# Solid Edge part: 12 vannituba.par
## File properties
Author: Henri
Template: Normal.par
Last saved by: Henri
Revision: 11
Application: Solid Edge
Accuracy: 0,990
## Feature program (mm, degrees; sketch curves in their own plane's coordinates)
sketch for "unnamed Protrusion 1" plane through (0, 0, 0) normal (0, 0, 1) x-axis (1, 0, 0)
  line (40, -40) -> (-40, -40)
  line (-40, -40) -> (-40, 40)
  line (-40, 40) -> (40, 40)
  line (40, 40) -> (40, -40)
extrude "unnamed Protrusion 1" add finite 15 along -normal
sketch for "ExtrudedCutout_1" plane through (0, 0, 0) normal (0, 0, 1) x-axis (0, 1, 0)
  line (-37.5, 37.5) -> (37.5, 37.5)
  line (37.5, 37.5) -> (37.5, -37.5)
  line (37.5, -37.5) -> (-37.5, -37.5)
  line (-37.5, -37.5) -> (-37.5, 37.5)
extrude "ExtrudedCutout_1" cut finite 5 along -normal
sketch for "ExtrudedProtrusion_2" #1 plane through (0, 0, 0) normal (0, 0, 1) x-axis (0, 1, 0)
  line (-40, 40) -> (40, 40)
  line (40, 40) -> (40, -40)
  line (40, -40) -> (-40, -40)
  line (-40, -40) -> (-40, 40)
sketch for "ExtrudedProtrusion_2" #2 plane through (0, 0, 0) normal (0, 0, 1) x-axis (0, 1, 0)
  line (-37.5, 37.5) -> (37.5, 37.5)
  line (37.5, 37.5) -> (37.5, -37.5)
  line (37.5, -37.5) -> (-37.5, -37.5)
  line (-37.5, -37.5) -> (-37.5, 37.5)
extrude "ExtrudedProtrusion_2" add finite 110 along +normal
sketch for "unnamed Cutout 1" plane through (40, 0, 50) normal (1, 0, 0) x-axis (0, 1, 0)
  line (-7.5, 47.5) -> (-7.5, -47.5)
  arc centre (-10, -47.5) radius 2.5 from (-10, -50) to (-7.5, -47.5) ccw
  line (-10, -50) -> (-30, -50)
  arc centre (-30, -47.5) radius 2.5 from (-32.5, -47.5) to (-30, -50) ccw
  line (-32.5, -47.5) -> (-32.5, 47.5)
  arc centre (-30, 47.5) radius 2.5 from (-32.5, 47.5) to (-30, 50) cw
  line (-30, 50) -> (-10, 50)
  arc centre (-10, 47.5) radius 2.5 from (-10, 50) to (-7.5, 47.5) cw
extrude "unnamed Cutout 1" cut through along -normal
sketch for "ExtrudedProtrusion_3" plane through (40, 0, 50) normal (1, 0, 0) x-axis (0, 1, 0)
  line (-5, 57.5) -> (-5, -55)
  line (-7.5, -55) -> (-5, -55)
  line (-7.5, 57.5) -> (-7.5, -55)
  line (-7.5, 57.5) -> (-5, 57.5)
extrude "ExtrudedProtrusion_3" add finite 40 along -normal
swept protrusion "unnamed SweptProtrusion 1"
sketch for "unnamed RevolvedProtrusion 1" plane through (0, 16.25, 0) normal (0, -1, 0) x-axis (1, 0, 0)
  line (21.829, 95.767) -> (26.5332, 94.073)
  line (26.5332, 94.073) -> (26.7357, 94.6352)
  arc centre (26.2653, 94.8046) radius 0.5 from (26.7357, 94.6352) to (26.5452, 95.2189) ccw
  arc centre (29.7321, 99.9349) radius 5.6918 from (24.229, 98.4814) to (26.5452, 95.2189) ccw
  arc centre (24.7124, 98.6091) radius 0.5 from (24.242, 98.7785) to (24.229, 98.4814) ccw
  line (24.5294, 99.5765) -> (24.242, 98.7785)
  line (24.5294, 99.5765) -> (23.3533, 100)
  line (23.3533, 100) -> (23.2686, 99.7648)
  line (24.2095, 99.426) -> (23.2686, 99.7648)
  line (24.0068, 98.8632) -> (24.2095, 99.426)
  arc centre (24.7124, 98.6091) radius 0.75 from (23.9873, 98.4175) to (24.0068, 98.8632) cw
  arc centre (29.7321, 99.9349) radius 5.9418 from (26.4053, 95.0118) to (23.9873, 98.4175) cw
  arc centre (26.2653, 94.8046) radius 0.25 from (26.5005, 94.7199) to (26.4053, 95.0118) ccw
  line (26.3827, 94.3929) -> (26.5005, 94.7199)
  line (21.9137, 96.0023) -> (26.3827, 94.3929)
  line (21.9137, 96.0023) -> (21.829, 95.767)
revolve "unnamed RevolvedProtrusion 1" add finite 360 deg
sketch for "ExtrudedProtrusion_4" #1 plane through (32.5, 0, 0) normal (1, 0, 0) x-axis (0, 1, 0)
  circle centre (16.25, 85) radius 1
sketch for "ExtrudedProtrusion_4" #2 plane through (32.5, 0, 0) normal (1, 0, 0) x-axis (0, 1, 0)
  circle centre (16.25, 40) radius 1
extrude "ExtrudedProtrusion_4" add finite 7.5 along +normal
sketch for "ExtrudedProtrusion_5" plane through (32.5, 0, 0) normal (1, 0, 0) x-axis (0, 1, 0)
  circle centre (16.25, 40) radius 1
extrude "ExtrudedProtrusion_5" add finite 2.5 along -normal
fillet "Round_1" radius 0.1
sketch for "unnamed Cutout 2" #1 plane through (21.829, 16.25, 95.767) normal (-0.338814, 0, -0.940853) x-axis (0, 1, 0)
  circle centre (-1.15, 0) radius 0.125
sketch for "unnamed Cutout 2" #2 plane through (21.829, 16.25, 95.767) normal (-0.338814, 0, -0.940853) x-axis (0, 1, 0)
  circle centre (-2, 0) radius 0.125
sketch for "unnamed Cutout 2" #3 plane through (21.829, 16.25, 95.767) normal (-0.338814, 0, -0.940853) x-axis (0, 1, 0)
  circle centre (-2.75, 0) radius 0.125
sketch for "unnamed Cutout 2" #4 plane through (21.829, 16.25, 95.767) normal (-0.338814, 0, -0.940853) x-axis (0, 1, 0)
  circle centre (-3.5, 0) radius 0.125
sketch for "unnamed Cutout 2" #5 plane through (21.829, 16.25, 95.767) normal (-0.338814, 0, -0.940853) x-axis (0, 1, 0)
  circle centre (-4.25, 0) radius 0.125
extrude "unnamed Cutout 2" cut through along -normal
pattern "Pattern_1" of "unnamed Cutout 2" along a curve  XDirCount = 15; XDirSpacing = 50 mm
extrude "unnamed Cutout 3" cut through
extrude "unnamed Cutout 4" cut through
extrude "unnamed Cutout 5" cut through
extrude "unnamed Cutout 6" cut through
extrude "unnamed Cutout 7" cut through
extrude "unnamed Cutout 8" cut through
sketch for "unnamed Cutout 9" #3
  line (47.5, 15.75) -> (47.5, 13.25)
  line (45, 10.75) -> (32.5, 10.75)
  arc centre (45, 13.25) radius 2.5 from (45, 10.75) to (47.5, 13.25) ccw
extrude "unnamed Cutout 9" cut through
extrude "unnamed Cutout 10" cut through
extrude "unnamed Cutout 11" cut through
extrude "unnamed Cutout 12" cut through
extrude "unnamed Cutout 13" cut through
extrude "unnamed Cutout 14" cut through
extrude "unnamed Cutout 15" cut through
extrude "unnamed Cutout 16" cut through
sketch for "ExtrudedProtrusion_7" plane through (30, 16.25, 40) normal (-1, 0, 0) x-axis (0, -1, 0)
  line (-4.75, 1.25) -> (4.75, 1.25)
  arc centre (4.75, 1) radius 0.25 from (4.75, 1.25) to (5, 1) cw
  line (5, 1) -> (5, -1)
  arc centre (4.75, -1) radius 0.25 from (4.75, -1.25) to (5, -1) ccw
  line (4.75, -1.25) -> (-4.75, -1.25)
  arc centre (-4.75, -1) radius 0.25 from (-5, -1) to (-4.75, -1.25) ccw
  line (-5, 1) -> (-5, -1)
  arc centre (-4.75, 1) radius 0.25 from (-5, 1) to (-4.75, 1.25) cw
extrude "ExtrudedProtrusion_7" add finite 3 along +normal
fillet "Round_4" radius 0.1
lofted protrusion "unnamed LoftedProtrusion 1"
lofted protrusion "unnamed LoftedProtrusion 2"
fillet "Round_5" radius 0.1
lofted cutout "unnamed LoftedCutout 1"
sketch for "unnamed Cutout 17" #1 plane through (0, 0, -5) normal (0, 0, 1) x-axis (1, 0, 0)
  circle centre (26.5, 16.25) radius 0.25
sketch for "unnamed Cutout 17" #2 plane through (0, 0, -5) normal (0, 0, 1) x-axis (1, 0, 0)
  circle centre (27.5, 16.25) radius 0.25
extrude "unnamed Cutout 17" cut through along -normal
pattern "Pattern_6" of "unnamed Cutout 17" along a curve  XDirCount = 8; XDirSpacing = 50 mm
extrude "unnamed Cutout 18" cut through
extrude "unnamed Cutout 19" cut through
extrude "unnamed Cutout 20" cut through
extrude "unnamed Cutout 21" cut through
extrude "unnamed Cutout 22" cut through
extrude "unnamed Cutout 23" cut through
extrude "unnamed Cutout 24" cut through
sketch for "unnamed Protrusion 2" plane through (0, 37.5, 52.5) normal (0, -1, 0) x-axis (1, 0, 0)
  circle centre (-30, 42.5) radius 0.75
extrude "unnamed Protrusion 2" add through along +normal
sketch for "RevolvedProtrusion_6" plane through (-37.5, 0, 52.5) normal (1, 0, 0) x-axis (0, 1, 0)
  line (0, 0) -> (0, 0)
  line (0, 0) -> (0, 0)
  line (-37.5, -30) -> (-14, -30)
  arc centre (-14, -31.5) radius 1.5 from (-14, -30) to (-12.5, -31.5) cw
  line (-12.5, -31.5) -> (-12.5, -36)
  arc centre (-14, -36) radius 1.5 from (-12.5, -36) to (-14, -37.5) cw
  line (-28.4376, -37.5) -> (-14, -37.5)
  arc centre (-28.4376, -39) radius 1.5 from (-29.2101, -37.7142) to (-28.4376, -37.5) cw
  line (-29.2101, -37.7142) -> (-37.5, -42.6952)
  line (-37.5, -42.6952) -> (-37.5, -32.5)
  line (-37.5, -30) -> (-37.5, -32.5)
revolve "RevolvedProtrusion_6" add finite 90 deg
sketch for "unnamed Protrusion 3" plane through (-37.5, 0, 52.5) normal (1, 0, 0) x-axis (0, 1, 0)
  line (-37.5, 55) -> (37.5, 55)
  line (37.5, 55) -> (37.5, 57.5)
  line (-37.5, 57.5) -> (37.5, 57.5)
  line (-37.5, 57.5) -> (-37.5, 55)
extrude "unnamed Protrusion 3" add through along +normal
sketch for "unnamed RevolvedProtrusion 2" plane through (0, 21.25, 0) normal (0, -1, 0) x-axis (1, 0, 0)
revolve "unnamed RevolvedProtrusion 2" add finite 360 deg
sketch for "unnamed Protrusion 4" #1 plane through (40, 0, 47.5) normal (1, 0, 0) x-axis (0, 1, 0)
sketch for "unnamed Protrusion 4" #2 plane through (40, 0, 47.5) normal (1, 0, 0) x-axis (0, 1, 0)
extrude "unnamed Protrusion 4" add through along +normal
swept protrusion "unnamed SweptProtrusion 2"
swept cutout "unnamed SweptCutout 1"
fillet "Round_7" radius 0.25
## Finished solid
Body 1: solid body, 289 faces, 615 edges, 240 vertices.
  Faces by surface: cylinder 170, plane 72, torus 23, sphere 16, spline 7, cone 1
  Edges by curve: circle 333, line 241, ellipse 25, intersection 16
Bounding box of the edges (mm; curved faces can reach further): 102.500 x 80.000 x 125.000, from (-40, -40, -15) to (62.5, 40, 110).
Cylindrical faces by radius (mm): R0.1 x48, R0.125 x75, R0.25 x20, R0.75 x1, R1 x12, R1.25 x1, R1.5 x4, R2.5 x4, R4.75 x1, R5 x1, R9.25 x1, R10 x1, R25 x1
Conical faces (half-angle, radius in mm at the cone's reference point): 59.0002 deg R8.2899 x1
Toroidal faces (ring radius, tube radius in mm): R0.15 r0.1 x8, R1.75 r0.5 x1, R1.75 r0.75 x1, R2.5 r1 x3, R4.5 r0.25 x1, R4.5 r0.5 x1, R4.9 r0.1 x1, R6.0236 r5.6918 x1, R6.0236 r5.9418 x1, R9.0624 r1.5 x1, R9.75 r0.25 x2, R23.5 r1.5 x2
Spherical faces by radius (mm): R0.1 x16
Planar faces by outward normal: +x 3, +y 7, +z 11, -x 5, -y 6, -z 10, oblique 30
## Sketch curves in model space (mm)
line (-37.5, 37.5, 107.5) -> (-37.5, 37.5, 110)
line (-37.5, -37.5, 110) -> (-37.5, 37.5, 110)
line (-37.5, -37.5, 110) -> (-37.5, -37.5, 107.5)
line (-37.5, -37.5, 107.5) -> (-37.5, 37.5, 107.5)
circle centre (52.5, 21.25, 90) radius 10
circle centre (52.5, 21.25, 90) radius 10
line (52.5, 6.1182, 90) -> (52.5, 32.5794, 90)
line (42.5, 7.4948, 90) -> (42.5, 28.6025, 90)
line (34.1854, 21.25, 90) -> (71.9652, 21.25, 90)
arc centre (-37.5, -14, 21) radius 1.5 from (-37.5, -14, 22.5) through (-37.5, -12.9089, 22.0294) to (-37.5, -12.5, 21)
line (-37.5, -12.5, 21) -> (-37.5, -12.5, 16.5)
arc centre (-37.5, -14, 16.5) radius 1.5 from (-37.5, -12.5, 16.5) through (-37.5, -12.9706, 15.4089) to (-37.5, -14, 15)
line (-37.5, -28.4376, 15) -> (-37.5, -14, 15)
arc centre (-37.5, -28.4376, 13.5) radius 1.5 from (-37.5, -29.2101, 14.7858) through (-37.5, -28.8384, 14.9454) to (-37.5, -28.4376, 15)
line (-37.5, -29.2101, 14.7858) -> (-37.5, -37.5, 9.8048)
line (-37.5, -37.5, 9.8048) -> (-37.5, -37.5, 20)
line (-37.5, -37.5, 22.5) -> (-37.5, -37.5, 20)
line (-37.5, -37.5, 22.5) -> (-37.5, -14, 22.5)
circle centre (-30, 37.5, 95) radius 0.75
line (52.5, 21.25, 79.2731) -> (52.5, 21.25, 33.9638)
line (52.5, 21.25, 90) -> (52.5, 21.25, 89.25)
line (43.25, 21.25, 89.25) -> (52.5, 21.25, 89.25)
line (43.25, 21.25, 15.75) -> (43.25, 21.25, 89.25)
line (52.5, 21.25, 15.75) -> (43.25, 21.25, 15.75)
line (52.5, 21.25, 15.75) -> (52.5, 21.25, 15)
line (52.5, 21.25, 15) -> (42.5, 21.25, 15)
line (42.5, 21.25, 15) -> (42.5, 21.25, 90)
line (42.5, 21.25, 90) -> (52.5, 21.25, 90)
arc centre (27.5, 17.25, -15) radius 0.5 from (27, 17.25, -15) through (27.1569, 17.6137, -15) to (27.5, 17.75, -15)
line (27.5, 17.75, -15) -> (29.5, 17.75, -15)
arc centre (29.5, 17.25, -15) radius 0.5 from (29.5, 17.75, -15) through (29.8637, 17.5931, -15) to (30, 17.25, -15)
line (30, 17.25, -15) -> (30, 15.25, -15)
arc centre (29.5, 15.25, -15) radius 0.5 from (29.5, 14.75, -15) through (29.8637, 14.9069, -15) to (30, 15.25, -15)
line (29.5, 14.75, -15) -> (27.5, 14.75, -15)
arc centre (27.5, 15.25, -15) radius 0.5 from (27, 15.25, -15) through (27.1569, 14.8863, -15) to (27.5, 14.75, -15)
line (27, 15.25, -15) -> (27, 17.25, -15)
arc centre (26.5, 14.25, -6) radius 0.5 from (26.5, 13.75, -6) through (26.1363, 13.9069, -6) to (26, 14.25, -6)
line (26, 14.25, -6) -> (26, 18.25, -6)
arc centre (26.5, 18.25, -6) radius 0.5 from (26, 18.25, -6) through (26.1569, 18.6137, -6) to (26.5, 18.75, -6)
line (26.5, 18.75, -6) -> (30.5, 18.75, -6)
arc centre (30.5, 18.25, -6) radius 0.5 from (30.5, 18.75, -6) through (30.8637, 18.5931, -6) to (31, 18.25, -6)
line (31, 18.25, -6) -> (31, 14.25, -6)
arc centre (30.5, 14.25, -6) radius 0.5 from (30.5, 13.75, -6) through (30.8637, 13.9069, -6) to (31, 14.25, -6)
line (30.5, 13.75, -6) -> (26.5, 13.75, -6)
circle centre (28.5, 16.25, -5) radius 2
circle centre (28.5, 16.25, -5) radius 1
circle centre (26.5, 16.25, -5) radius 0.25
circle centre (26.5, 16.25, -5) radius 0.25
circle centre (27.5, 16.25, -5) radius 0.25
arc centre (30.5, 18.25, -5) radius 0.5 from (30.5, 18.75, -5) through (30.8637, 18.5931, -5) to (31, 18.25, -5)
line (31, 18.25, -5) -> (31, 14.25, -5)
arc centre (30.5, 14.25, -5) radius 0.5 from (30.5, 13.75, -5) through (30.8637, 13.9069, -5) to (31, 14.25, -5)
line (30.5, 13.75, -5) -> (26.5, 13.75, -5)
arc centre (26.5, 14.25, -5) radius 0.5 from (26.5, 13.75, -5) through (26.1363, 13.9069, -5) to (26, 14.25, -5)
line (26, 14.25, -5) -> (26, 18.25, -5)
arc centre (26.5, 18.25, -5) radius 0.5 from (26, 18.25, -5) through (26.1569, 18.6137, -5) to (26.5, 18.75, -5)
line (26.5, 18.75, -5) -> (30.5, 18.75, -5)
line (27, 21.5, 44.75) -> (27, 21, 44.75)
line (26.5, 21, 44.75) -> (27, 21, 44.75)
line (26.5, 18, 44.75) -> (26.5, 21, 44.75)
line (27, 18, 44.75) -> (26.5, 18, 44.75)
line (27, 18, 44.75) -> (27, 17.5, 44.75)
line (27, 17.5, 44.75) -> (30, 17.5, 44.75)
line (30, 17.5, 44.75) -> (30, 18, 44.75)
line (30.5, 18, 44.75) -> (30, 18, 44.75)
line (30.5, 21, 44.75) -> (30.5, 18, 44.75)
line (30, 21, 44.75) -> (30.5, 21, 44.75)
line (30, 21, 44.75) -> (30, 21.5, 44.75)
line (30, 21.5, 44.75) -> (27, 21.5, 44.75)
line (30, 15, 44.75) -> (30, 14.5, 44.75)
line (30, 14.5, 44.75) -> (30.5, 14.5, 44.75)
line (30.5, 14.5, 44.75) -> (30.5, 11.5, 44.75)
line (30.5, 11.5, 44.75) -> (30, 11.5, 44.75)
line (30, 11.5, 44.75) -> (30, 11, 44.75)
line (30, 11, 44.75) -> (27, 11, 44.75)
line (27, 11, 44.75) -> (27, 11.5, 44.75)
line (27, 11.5, 44.75) -> (26.498, 11.5, 44.75)
line (26.498, 11.5, 44.75) -> (26.498, 14.5, 44.75)
line (26.498, 14.5, 44.75) -> (27, 14.5, 44.75)
line (27, 14.5, 44.75) -> (27, 15, 44.75)
line (27, 15, 44.75) -> (30, 15, 44.75)
line (45, 16.25, 10.75) -> (32.5, 16.25, 10.75)
arc centre (45, 16.25, 13.25) radius 2.5 from (45, 16.25, 10.75) through (46.8184, 16.25, 11.5344) to (47.5, 16.25, 13.25)
line (47.5, 16.25, 15.75) -> (47.5, 16.25, 13.25)
line (30.4876, 13, 41.25) -> (26.1728, 13, 41.25)
line (30.4876, 19.5, 41.25) -> (26.5407, 19.5, 41.25)
line (28.5, 22.1775, 41.25) -> (28.5, 10.6903, 41.25)
line (29.75, 18.75, 41.25) -> (29.25, 18.75, 41.25)
line (29.25, 18.25, 41.25) -> (29.25, 18.75, 41.25)
line (27.75, 18.25, 41.25) -> (29.25, 18.25, 41.25)
line (27.75, 18.75, 41.25) -> (27.75, 18.25, 41.25)
line (27.75, 18.75, 41.25) -> (27.25, 18.75, 41.25)
line (27.25, 18.75, 41.25) -> (27.25, 20.25, 41.25)
line (27.25, 20.25, 41.25) -> (27.75, 20.25, 41.25)
line (27.75, 20.75, 41.25) -> (27.75, 20.25, 41.25)
line (29.25, 20.75, 41.25) -> (27.75, 20.75, 41.25)
line (29.25, 20.25, 41.25) -> (29.25, 20.75, 41.25)
line (29.25, 20.25, 41.25) -> (29.75, 20.25, 41.25)
line (29.75, 20.25, 41.25) -> (29.75, 18.75, 41.25)
line (29.25, 11.75, 41.25) -> (27.75, 11.75, 41.25)
line (27.75, 11.75, 41.25) -> (27.75, 12.25, 41.25)
line (27.75, 12.25, 41.25) -> (27.248, 12.25, 41.25)
line (27.248, 12.25, 41.25) -> (27.248, 13.75, 41.25)
line (27.248, 13.75, 41.25) -> (27.75, 13.75, 41.25)
line (27.75, 13.75, 41.25) -> (27.75, 14.25, 41.25)
line (27.75, 14.25, 41.25) -> (29.25, 14.25, 41.25)
line (29.25, 14.25, 41.25) -> (29.25, 13.75, 41.25)
line (29.25, 13.75, 41.25) -> (29.75, 13.75, 41.25)
line (29.75, 13.75, 41.25) -> (29.75, 12.25, 41.25)
line (29.75, 12.25, 41.25) -> (29.25, 12.25, 41.25)
line (29.25, 12.25, 41.25) -> (29.25, 11.75, 41.25)
circle centre (47.5, 16.25, 15.75) radius 1
circle centre (47.5, 16.25, 15.75) radius 1.25
line (47.5, 16.25, 15.75) -> (47.5, 16.25, 13.25)
arc centre (45, 16.25, 13.25) radius 2.5 from (45, 16.25, 10.75) through (46.8184, 16.25, 11.5344) to (47.5, 16.25, 13.25)
line (45, 16.25, 10.75) -> (32.5, 16.25, 10.75)
line (32.5, 16.25, 102.5) -> (32.5, 16.25, 10.75)
arc centre (30, 16.25, 102.5) radius 2.5 from (30, 16.25, 105) through (31.8184, 16.25, 104.2156) to (32.5, 16.25, 102.5)
line (30, 16.25, 105) -> (26.9108, 16.25, 105)
arc centre (26.9108, 16.25, 102.5) radius 2.5 from (24.5586, 16.25, 103.347) through (25.5336, 16.25, 104.5865) to (26.9108, 16.25, 105)
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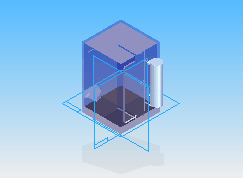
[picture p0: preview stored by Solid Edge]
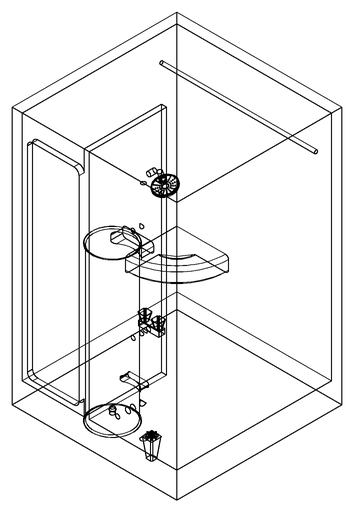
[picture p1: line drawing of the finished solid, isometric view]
